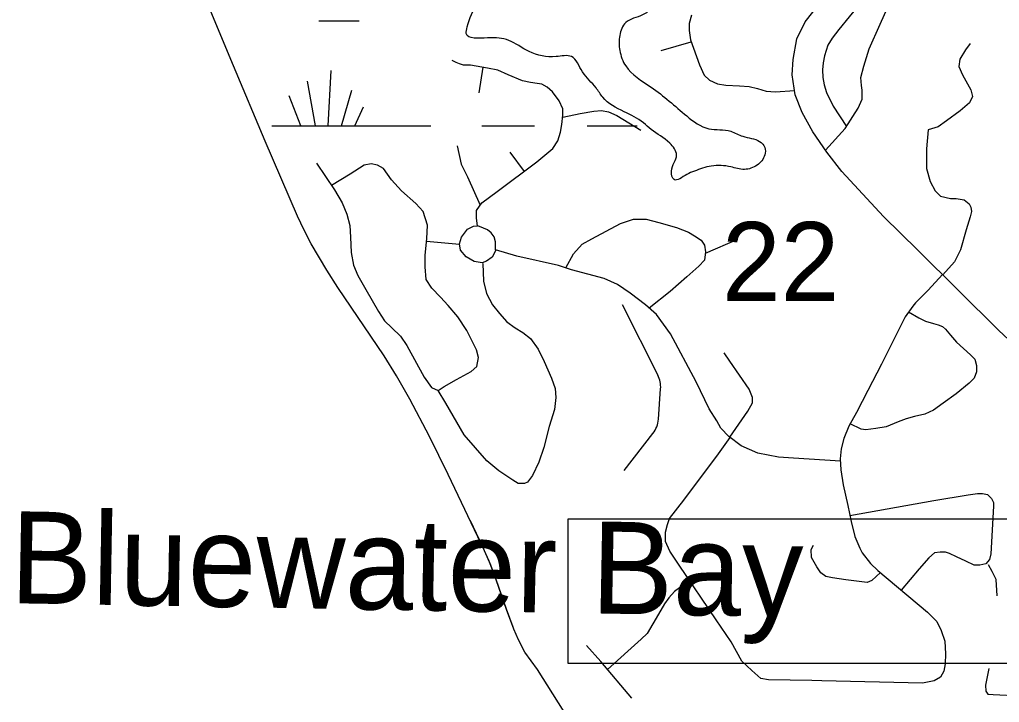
# Model space of a CAD drawing. Extents: x 1219626 to 1426462, y 456797 to 752399.
# Drawn here: x 1354861 to 1360454, y 541593 to 545489 of the extents above; entities that cross this region are included whole.
import ezdxf

# ---------------------------------------------------------------- set-up
doc = ezdxf.new("R2010")
doc.units = 0
for name, color, linetype in [('Communities and Subdivisions Names without Post Office', 7, 'Continuous'), ('Lakes and Ponds', 7, 'Continuous'), ('Local Roads Paved', 7, 'Continuous'), ('Masks', 7, 'Continuous'), ('Section Numbers', 7, 'Continuous'), ('State Routes Highway Center Lines', 7, 'Continuous'), ('Swamps', 7, 'Continuous')]:
    doc.layers.add(name, color=color, linetype=linetype)

msp = doc.modelspace()

# ---------------------------------------------------------------- linework, layer by layer
at = {"layer": 'Lakes and Ponds'}
msp.add_lwpolyline([(1357991.9, 541503.2), (1357816.8, 541781.4), (1357780.4, 541830.5), (1357745.3, 541880.6), (1357709.5, 541949.6), (1357681.9, 542011.7), (1357639.6, 542123.1), (1357581.3, 542292.4), (1357550.2, 542376.2), (1357515.1, 542458.3), (1357307.5, 542893.8), (1357199.8, 543109.7), (1357088.3, 543323.7), (1357012.4, 543456.7), (1356941, 543570.4), (1356678, 543960.6), (1356614.6, 544059.3), (1356525.6, 544210.7), (1356484.9, 544288.4), (1356447.2, 544367.8), (1356261.9, 544795.4), (1356082, 545225.3), (1355780.4, 545948.5)], dxfattribs=at)
msp.add_spline([(1358707.7, 546101.5), (1358799.7, 546149.9), (1358857.7, 546169.3), (1358896.4, 546222.5), (1358998.1, 546309.7), (1359094.8, 546319.4), (1359191.6, 546377.5), (1359293.3, 546367.8), (1359322.3, 546304.8), (1359269.1, 546275.8), (1359167.4, 546227.4), (1359104.5, 546198.3), (1359056.1, 546193.5), (1359017.4, 546120.9), (1358959.3, 546057.9), (1358906.1, 546033.7), (1358833.5, 545980.5), (1358736.7, 545898.1), (1358664.2, 545791.6), (1358557.7, 545670.6), (1358470.6, 545554.4), (1358417.3, 545515.7), (1358320.6, 545472.1), (1358286.7, 545399.5), (1358286.7, 545312.3), (1358320.6, 545225.2), (1358465.7, 545104.1), (1358669, 544939.5), (1358794.8, 544866.9), (1358920.6, 544852.3), (1358988.4, 544823.3), (1359085.2, 544794.2), (1359114.2, 544760.4), (1359114.2, 544716.8), (1359070.6, 544658.7), (1358998.1, 544634.5), (1358920.6, 544649), (1358809.3, 544653.8), (1358712.5, 544624.8), (1358669, 544605.4), (1358596.4, 544576.4), (1358581.9, 544624.8), (1358610.9, 544716.8), (1358572.2, 544784.6), (1358465.7, 544862), (1358422.2, 544900.8), (1358310.9, 544963.7), (1358189.9, 545046), (1358151.2, 545099.3), (1358073.8, 545191.3), (1358010.8, 545278.4), (1357923.7, 545278.4), (1357768.9, 545307.5), (1357652.7, 545370.4), (1357531.8, 545384.9), (1357410.8, 545409.1), (1357415.6, 545447.9), (1357468.9, 545583.4), (1357531.8, 545723.8)], degree=3, dxfattribs=at)
at = {"layer": 'Local Roads Paved'}
for p, q in [((1358523.7, 545313.3), (1358694.2, 545362)), ((1357504.2, 545217.2), (1357482.2, 545071.5)), ((1357659.1, 544732.5), (1357741.5, 544623.3)), ((1357184.3, 544225.2), (1357371.7, 544207.7)), ((1358775.8, 544157.5), (1358961.2, 544236.6)), ((1358300.5, 543863.6), (1358504.1, 543460.8)), ((1358507.5, 543209.1), (1358519.8, 543382.4)), ((1358311.6, 542917.2), (1358476, 543127.4))]:
    msp.add_line(p, q, dxfattribs=at)
for points in [[(1360534.9, 543637.4), (1360450.9, 543714.5), (1359988.8, 544174), (1359792, 544365.6), (1359553.6, 544622.2), (1359468.6, 544733.2), (1359388, 544849.3), (1359328.2, 544958.6), (1359288.3, 545060.9), (1359271, 545173.6), (1359276.2, 545261.1), (1359297.8, 545379), (1359345.5, 545476.1), (1359460.8, 545624.4), (1359723.5, 545920)], [(1359460.4, 544745), (1359572.6, 544867.1), (1359648.1, 544984.1), (1359670.6, 545034.4), (1359669.7, 545087.3), (1359667.1, 545114.2), (1359662.8, 545158.4), (1359680.1, 545224.3), (1359710.5, 545323.1), (1359772.9, 545463.6), (1359832.7, 545594.5), (1359859.6, 545630), (1359917.7, 545661.2), (1359963.6, 545683.8), (1359993.1, 545709.8), (1360019.2, 545776.2)], [(1359873.4, 545637.4), (1359816.3, 545675.1), (1359780.7, 545692.4), (1359753, 545692.4), (1359720, 545656.9), (1359596.9, 545505.2), (1359537.1, 545432.4), (1359499, 545383.8), (1359474.7, 545343.1), (1359454.7, 545282.4), (1359446.9, 545243.4), (1359443.5, 545203.5), (1359445.2, 545159.3), (1359453.9, 545117.7), (1359466, 545074.3), (1359505, 544996.3), (1359580.3, 544879)], [(1358697, 545513.8), (1358682.3, 545467), (1358682.3, 545426.3), (1358690.1, 545373.4), (1358741.3, 545230.4), (1358768.1, 545173.1), (1358799.3, 545143.7), (1358844.4, 545122), (1358892.1, 545115.1), (1358970.1, 545110.7), (1359024.7, 545107.2), (1359073.3, 545096), (1359121.8, 545081.2), (1359176.5, 545077.8), (1359284.7, 545084.2)], [(1360286.1, 545352.2), (1360261, 545316.6), (1360228.5, 545262.9), (1360221.5, 545221.3), (1360242.4, 545174.4), (1360290, 545087.7), (1360299.6, 545050.5), (1360284, 545014.9), (1360229.3, 544968.1), (1360152.2, 544912.6), (1360104.5, 544877.1), (1360047.3, 544859.7)], [(1359546.1, 542969.5), (1359277.7, 542987.4), (1359193.6, 542993.4), (1359075.7, 543016), (1358980.3, 543057.6), (1358908.4, 543111.3), (1358864.1, 543158.2), (1358839.9, 543198.9), (1358797.4, 543268.3), (1358722.8, 543422.6), (1358575.5, 543695.7), (1358496.6, 543806.6), (1358433.3, 543861.2), (1358346.6, 543928.9), (1358273.8, 543977.4), (1358198.3, 544011.2), (1358011.9, 544062.4), (1357937.4, 544085.8), (1357699.8, 544138.7), (1357576.7, 544175.1), (1357576.7, 544221), (1357568.9, 544250.5), (1357553.3, 544272.2), (1357530.8, 544290.4), (1357486.6, 544309.5), (1357475.3, 544312.1), (1357468.4, 544356.3), (1357469.2, 544400.5), (1357498.7, 544443.8), (1357587.1, 544508), (1357813.4, 544677), (1357905.3, 544754.2), (1357933.1, 544798.4), (1357947.8, 544847), (1357955.6, 544891.2), (1357962.5, 544943.2), (1357962.5, 544980.5), (1357940.9, 545025.5), (1357902.7, 545076.7), (1357872.4, 545104.4), (1357841.2, 545121.8), (1357815.1, 545125.2), (1357777, 545129.6), (1357731.1, 545140.8), (1357649.6, 545174.7), (1357590.6, 545201.5), (1357531.7, 545212.8), (1357433.7, 545228.4), (1357394.7, 545228.4), (1357371.3, 545237.1), (1357353.1, 545244), (1357330.5, 545255.3)], [(1357961.2, 544933.4), (1358061.4, 544953.6), (1358138.5, 544967.5), (1358182.7, 544970.9), (1358222.6, 544963.1), (1358270.3, 544941.4), (1358407.3, 544859.1)], [(1360047.3, 544859.7), (1360038.6, 544752.2), (1360036.9, 544639.5), (1360057.7, 544565), (1360087.2, 544513), (1360118.4, 544481.8), (1360173.9, 544467.9), (1360206.8, 544468.8), (1360251.9, 544460.1), (1360280.5, 544437.5), (1360290.9, 544419.3), (1360295.2, 544394.2), (1360286.6, 544363), (1360263.2, 544290.2), (1360231.1, 544174.9), (1360198.1, 544106.4), (1360130.4, 544033.2)], [(1357358.3, 544768.9), (1357381.7, 544664), (1357418.1, 544592.1), (1357489.5, 544430.2)], [(1356554.6, 544669.2), (1356658.7, 544518.4), (1356702.9, 544443.8), (1356728, 544378.8), (1356746.2, 544313.8), (1356750.5, 544247), (1356754, 544160.3), (1356766.2, 544087.5), (1356791.3, 544029.4), (1356836.4, 543948.8), (1356909.2, 543823.1), (1356943, 543771.1), (1356984.6, 543730.3), (1357034.9, 543682.7), (1357071.3, 543628.9), (1357171, 543449.5), (1357211.8, 543389.6), (1357250.8, 543372.3)], [(1357505.7, 544097.9), (1357508.3, 543997.4), (1357525.6, 543927.1), (1357560.3, 543862.1), (1357599.3, 543811.8), (1357641.8, 543764.1), (1357689.4, 543730.3), (1357732.8, 543703.5), (1357777, 543669.7), (1357820.3, 543609), (1357854.2, 543538.7), (1357896.6, 543443.4), (1357917.4, 543384.4), (1357922.6, 543332.4), (1357914.8, 543263.9), (1357884.5, 543167.7), (1357853.3, 543047.2), (1357825.6, 542963.1), (1357789.1, 542888.5), (1357760.5, 542849.5), (1357742.3, 542842.6), (1357707.6, 542841.7), (1357675.6, 542860.8), (1357596.7, 542914.6), (1357527.3, 542970.9), (1357398.2, 543120), (1357294.1, 543301.2), (1357250.8, 543372.3), (1357283.7, 543396.6), (1357354.8, 543435.6), (1357438, 543480.7), (1357470.1, 543510.1), (1357479.6, 543560.4), (1357468.4, 543604.6), (1357414.6, 543715.6), (1357362.6, 543792.8), (1357306.3, 543857.8), (1357263.8, 543906.3), (1357214.4, 543956.6), (1357182.3, 544006), (1357176.2, 544078.8), (1357176.2, 544145.6), (1357185.8, 544239.2), (1357189.2, 544315.5), (1357164.9, 544394.4), (1357123.3, 544440.4), (1357040.1, 544512.3), (1356983.8, 544575.6), (1356937.8, 544639.8), (1356904, 544658), (1356866.7, 544665.8), (1356826.8, 544658.8), (1356747.9, 544606.8), (1356642, 544542.5)], [(1357979, 544072.7), (1358023.2, 544152.5), (1358072.6, 544207.2), (1358126.4, 544237.5), (1358291.1, 544325.1), (1358364.8, 544350.2), (1358436.7, 544350.2), (1358510.4, 544332), (1358611, 544303.4), (1358679.5, 544276.5), (1358712.4, 544255.7), (1358750.6, 544230.6), (1358769.6, 544202.8), (1358776.6, 544163.8), (1358770.5, 544117), (1358738.4, 544083.2), (1358669.9, 544020.8), (1358574.6, 543937.5), (1358454.6, 543842.9)], [(1357578.4, 544174.6), (1357558.5, 544134.3), (1357526.5, 544110.1), (1357501.3, 544100.5), (1357455.4, 544108.3), (1357409.4, 544136.1), (1357378.2, 544174.2), (1357371.3, 544209.8), (1357383.4, 544248.8), (1357418.1, 544293.8), (1357451, 544311.2), (1357475.3, 544312.4)], [(1360128.7, 544034.8), (1360047.3, 543946), (1359975.3, 543872.3), (1359958.9, 543855), (1359916.4, 543793.4), (1359864.4, 543690.2), (1359781.1, 543522.9), (1359702.3, 543373.8), (1359638.1, 543248.1), (1359594.8, 543170.1), (1359565.3, 543099.9), (1359551.4, 543040.9), (1359545.3, 542983.7), (1359548.8, 542919.5), (1359561.8, 542834.6), (1359588.7, 542715.8), (1359606.9, 542625.6), (1359629.4, 542539), (1359656.3, 542473.9), (1359671, 542446.2), (1359717.9, 542386.4), (1359759.5, 542346.5), (1360043.8, 542107.2), (1360095.8, 542054.3), (1360121.8, 542004.1), (1360142.7, 541942.5), (1360146.1, 541870.5), (1360144.4, 541812.5), (1360137.5, 541771.7), (1360117.5, 541737.9), (1360081.1, 541715.4), (1360015.2, 541703.2), (1359439.6, 541717.1), (1359382.4, 541718.8), (1359135.3, 541721.4), (1359091.9, 541730.1), (1359040.8, 541776), (1358984.4, 541828.9), (1358922, 541938.2), (1358836.2, 542064.7), (1358626.4, 542376), (1358571.8, 542456.6), (1358548.4, 542512.1), (1358547.5, 542565), (1358558.8, 542609.2), (1358570.9, 542642.1), (1358652.4, 542747.9), (1358850.9, 543011.4), (1358916.8, 543105)], [(1359935.8, 543821.5), (1359994.6, 543786.7), (1360031, 543768.5), (1360077, 543754.6), (1360104.7, 543747.7), (1360128.1, 543738.1), (1360146.3, 543722.5), (1360174.1, 543687.9), (1360208.8, 543648), (1360289.4, 543576), (1360314.5, 543550.9), (1360323.2, 543515.3), (1360323.2, 543478.9), (1360309.3, 543442.5), (1360281.6, 543413.9), (1360206.2, 543354.1), (1360132.5, 543301.2), (1360077, 543260.5), (1360028.4, 543237.9), (1359968.6, 543224.9), (1359920.9, 543211.9), (1359875, 543194.6), (1359807.4, 543166), (1359748.4, 543156.4), (1359691.2, 543148.6), (1359665.2, 543153), (1359601.7, 543182.5)], [(1358914.7, 543106.6), (1359018.2, 543254.2), (1359045.1, 543302.7), (1359045.1, 543332.2), (1359026, 543380.7), (1358915.9, 543540.3), (1358882.1, 543586.9)], [(1359600.1, 542659.4), (1360080.2, 542745.3), (1360276.2, 542778.2), (1360329, 542786), (1360356.8, 542786), (1360385.4, 542779.1), (1360408.8, 542756.6), (1360420.1, 542734), (1360420.1, 542713.2), (1360405.3, 542440.1), (1360396.7, 542408), (1360375.9, 542382.9), (1360341.2, 542376), (1360310, 542376.8), (1360261.4, 542399.4), (1360209.4, 542424.5), (1360168.7, 542441.9), (1360146.1, 542450.5), (1360116.6, 542450.5), (1360082.8, 542446.2), (1360051.6, 542417.6), (1359996.1, 542356), (1359893.5, 542233.7)], [(1359774.2, 542334.1), (1359726.5, 542288.4), (1359698.8, 542278), (1359577.4, 542292.7), (1359501.1, 542303.1), (1359463.8, 542311.8), (1359434.4, 542332.6), (1359411.8, 542367.3), (1359381.5, 542419.3), (1359378.9, 542466.1), (1359392.9, 542489.5)], [(1360440.2, 542201.1), (1360435, 542294.7), (1360411.6, 542339.8), (1360390.8, 542377.9)], [(1358685.2, 542288.7), (1358598.4, 542226.2), (1358567.2, 542189.8), (1358542.1, 542155.1), (1358507.4, 542096.2), (1358442.4, 541986.9), (1358408.6, 541954.9), (1358215.9, 541781.8)], [(1358354.8, 541617.6), (1358178, 541826.5), (1358097.3, 541918.4)], [(1360393, 541786), (1360374.8, 541691.5), (1360375.6, 541656.8), (1360388.6, 541640.4), (1360418.1, 541638.6), (1360572.4, 541630), (1360687.7, 541630), (1361014.6, 541624.8), (1361517.4, 541609.2), (1361894.5, 541597), (1361940.5, 541578)]]:
    msp.add_lwpolyline(points, dxfattribs=at)
for centre, start, end in [((1358370.2, 543393.1), 355.9164, 26.8107), ((1358357.8, 543219.8), 321.9666, 355.9164)]:
    msp.add_arc(centre, 150, start, end, dxfattribs=at)
at = {"layer": 'Masks'}
msp.add_lwpolyline([(1357432.9, 542630.7), (1357484.1, 542523.1), (1357539.9, 542400.3), (1357580, 542295.8), (1357638.6, 542126.1), (1357677.1, 542024.4)], dxfattribs=at)
at = {"layer": 'State Routes Highway Center Lines'}
msp.add_lwpolyline([(1357991.6, 542640.7), (1362239.6, 542640.7), (1362239.6, 541816), (1357991.6, 541816)], close=True, dxfattribs=at)
at = {"layer": 'Swamps'}
for p, q in [((1356569.2, 545482.8), (1356800, 545482.8)), ((1356621.5, 544882.9), (1356638.7, 545198.9)), ((1356550.5, 544882.9), (1356504.3, 545137.3)), ((1356465.4, 544883), (1356400, 545054.9)), ((1356698.2, 544883), (1356756.4, 545086.9)), ((1356774.8, 544883), (1356823.7, 544991.6)), ((1356300, 544882.8), (1357207.3, 544882.8)), ((1357500, 544882.8), (1357800, 544882.8)), ((1358100, 544882.8), (1358385.3, 544882.8))]:
    msp.add_line(p, q, dxfattribs=at)

# ---------------------------------------------------------------- texts
at = {"layer": 'Communities and Subdivisions Names without Post Office'}
msp.add_text('Bluewater Bay', height=525.002, rotation=358.9997, dxfattribs=at).set_placement((1354803.1, 542159.4))
at = {"layer": 'Section Numbers'}
msp.add_text('22', height=450, rotation=359.9997, dxfattribs=at).set_placement((1358870.5, 543884.3))

doc.saveas('drawing.dxf')
